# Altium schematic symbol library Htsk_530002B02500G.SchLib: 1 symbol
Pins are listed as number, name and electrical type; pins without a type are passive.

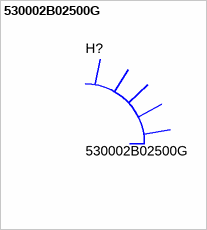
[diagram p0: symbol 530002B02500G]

## 530002B02500G
designator H?
HEATSINK TO-220 POWER W/PINS BK; Manufacturer: Aavid Thermalloy; SymbolCreator: a0414679; Attachment Method: Bolt On and PC Pin; Shape: Rectangular; Material Finish: Black Anodized; Thermal Resistance @ Natural: 2.6°C/W; Power Dissipation @ Temperature Rise: 20W @ 60°C; Thermal Resistance @ Forced Air Flow: 2.0°C/W @ 300 LFM
footprint HSINK_518-95AB
footprint Htsk_530002B02500G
